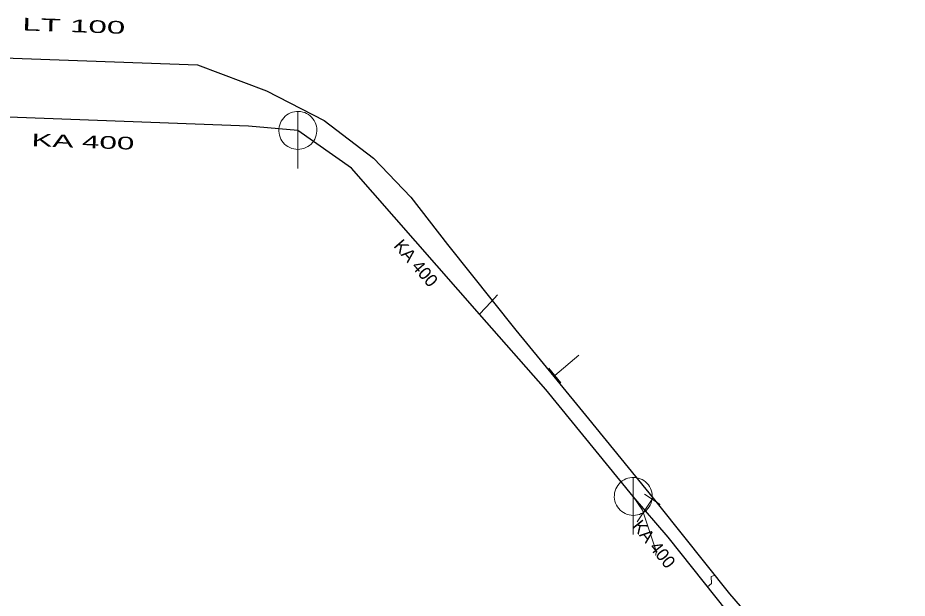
# Model space of a CAD drawing. Extents: x -688432 to -687974, y -973332 to -972704.
# Drawn here: x -688097.06 to -688050.24, y -972954.25 to -972923.69 of the extents above; entities that cross this region are included whole.
import ezdxf
from ezdxf.enums import TextEntityAlignment as Align

# ---------------------------------------------------------------- set-up
doc = ezdxf.new("R2010")
doc.units = 0
doc.header["$LTSCALE"] = 0.27
for name, color, linetype, lineweight in [('1', 7, 'Continuous', 25), ('11', 7, 'Continuous', 13), ('13', 7, 'Continuous', 13), ('14', 7, 'Continuous', 25), ('17', 7, 'Continuous', 25), ('22', 7, 'Continuous', 13), ('34', 7, 'Continuous', 13)]:
    doc.layers.add(name, color=color, linetype=linetype, lineweight=lineweight)

msp = doc.modelspace()

# ---------------------------------------------------------------- linework, layer by layer
at = {"layer": '11'}
for points in [[(-688071.809, -972938.28), (-688072.149, -972938.64), (-688072.75, -972939.3)], [(-688063.48, -972952), (-688063.449, -972951.77), (-688064.17, -972949.609), (-688064.66, -972948.89)], [(-688060.41, -972953.05), (-688060.559, -972953.1), (-688060.539, -972953.48), (-688060.75, -972953.649)]]:
    msp.add_lwpolyline(points, dxfattribs=at)
at = {"layer": '13'}
for p, q in [((-688068.793, -972942.522), (-688067.52, -972941.449)), ((-688063.661, -972949.042), (-688064.449, -972950.219))]:
    msp.add_line(p, q, dxfattribs=at)
at = {"layer": '14', "lineweight": 13}
for p, q in [((-688068.85, -972942.57), (-688068.793, -972942.522)), ((-688063.62, -972948.98), (-688063.661, -972949.042))]:
    msp.add_line(p, q, dxfattribs=at)
at = {"layer": '14'}
for points in [[(-688082.32, -972929.62), (-688084.92, -972929.39), (-688102.239, -972928.739)], [(-688064.66, -972948.89), (-688069.27, -972943.26), (-688072.75, -972939.3), (-688079.5, -972931.6), (-688082.32, -972929.62)], [(-688056.879, -972958.18), (-688059.07, -972955.76), (-688062.829, -972951.039), (-688064.66, -972948.89)]]:
    msp.add_lwpolyline(points, dxfattribs=at)
at = {"layer": '17'}
msp.add_lwpolyline([(-688142.539, -972926.989), (-688136.969, -972927.03), (-688124.52, -972926.469), (-688116.5, -972926.3), (-688115.02, -972926.289), (-688112.359, -972926.21), (-688100.73, -972925.699), (-688087.609, -972926.17), (-688083.969, -972927.539), (-688080.94, -972929.1), (-688078.329, -972931.09), (-688076.37, -972933.14), (-688074.449, -972935.62), (-688070.85, -972940.129), (-688068.85, -972942.57), (-688067.02, -972944.8), (-688063.62, -972948.98), (-688063.329, -972949.34), (-688059.6, -972954.02), (-688058.039, -972955.829), (-688055.76, -972958.48), (-688051.969, -972962.76), (-688050.239, -972964.93)], dxfattribs=at)
at = {"layer": '22'}
for p, q in [((-688082.32, -972931.62), (-688082.319, -972928.62)), ((-688064.66, -972950.89), (-688064.659, -972947.89))]:
    msp.add_line(p, q, dxfattribs=at)
for points in [[(-688081.32, -972929.62), (-688081.325, -972929.511), (-688081.343, -972929.403), (-688081.373, -972929.297), (-688081.413, -972929.196), (-688081.465, -972929.099), (-688081.527, -972929.009), (-688081.599, -972928.926), (-688081.679, -972928.852), (-688081.767, -972928.786), (-688081.861, -972928.731), (-688081.961, -972928.686), (-688082.066, -972928.653), (-688082.173, -972928.631), (-688082.282, -972928.621), (-688082.392, -972928.623), (-688082.5, -972928.637), (-688082.607, -972928.662), (-688082.71, -972928.699), (-688082.808, -972928.748), (-688082.9, -972928.806), (-688082.986, -972928.875), (-688083.063, -972928.952), (-688083.132, -972929.038), (-688083.191, -972929.13), (-688083.239, -972929.228), (-688083.276, -972929.331), (-688083.302, -972929.438), (-688083.316, -972929.546), (-688083.319, -972929.656), (-688083.309, -972929.765), (-688083.288, -972929.872), (-688083.254, -972929.976), (-688083.21, -972930.076), (-688083.155, -972930.171), (-688083.089, -972930.259), (-688083.015, -972930.339), (-688082.932, -972930.411), (-688082.842, -972930.473), (-688082.746, -972930.525), (-688082.644, -972930.566), (-688082.539, -972930.596), (-688082.431, -972930.614), (-688082.321, -972930.62), (-688082.212, -972930.614), (-688082.104, -972930.596), (-688081.999, -972930.567), (-688081.897, -972930.526), (-688081.8, -972930.474), (-688081.71, -972930.412), (-688081.627, -972930.341), (-688081.552, -972930.261), (-688081.487, -972930.173), (-688081.431, -972930.079), (-688081.387, -972929.979), (-688081.353, -972929.875), (-688081.331, -972929.767), (-688081.321, -972929.658)], [(-688063.66, -972948.89), (-688063.665, -972948.781), (-688063.683, -972948.673), (-688063.713, -972948.567), (-688063.753, -972948.466), (-688063.805, -972948.369), (-688063.867, -972948.279), (-688063.939, -972948.196), (-688064.019, -972948.122), (-688064.107, -972948.056), (-688064.201, -972948.001), (-688064.301, -972947.956), (-688064.406, -972947.923), (-688064.513, -972947.901), (-688064.622, -972947.891), (-688064.732, -972947.893), (-688064.84, -972947.907), (-688064.947, -972947.932), (-688065.05, -972947.969), (-688065.148, -972948.018), (-688065.24, -972948.076), (-688065.326, -972948.145), (-688065.403, -972948.222), (-688065.472, -972948.308), (-688065.531, -972948.4), (-688065.579, -972948.498), (-688065.616, -972948.601), (-688065.642, -972948.708), (-688065.656, -972948.816), (-688065.659, -972948.926), (-688065.649, -972949.035), (-688065.628, -972949.142), (-688065.594, -972949.246), (-688065.55, -972949.346), (-688065.495, -972949.441), (-688065.429, -972949.529), (-688065.355, -972949.609), (-688065.272, -972949.681), (-688065.182, -972949.743), (-688065.086, -972949.795), (-688064.984, -972949.836), (-688064.879, -972949.866), (-688064.771, -972949.884), (-688064.661, -972949.89), (-688064.552, -972949.884), (-688064.444, -972949.866), (-688064.339, -972949.837), (-688064.237, -972949.796), (-688064.14, -972949.744), (-688064.05, -972949.682), (-688063.967, -972949.611), (-688063.892, -972949.531), (-688063.827, -972949.443), (-688063.771, -972949.349), (-688063.727, -972949.249), (-688063.693, -972949.145), (-688063.671, -972949.037), (-688063.661, -972948.928)]]:
    msp.add_lwpolyline(points, close=True, dxfattribs=at)
at = {"layer": '34'}
for p, q in [((-688069.115, -972942.139), (-688068.471, -972942.904)), ((-688063.245, -972949.319), (-688064.076, -972948.763))]:
    msp.add_line(p, q, dxfattribs=at)

# ---------------------------------------------------------------- texts
at = {"layer": '1'}
for s, width, p in [('LT 100', 1.95, (-688094.1256, -972924.4473)), ('LT 100', 1.95, (-688094.1256, -972924.4473)), ('LT 100', 1.95, (-688094.1256, -972924.4473)), ('LT 100', 1.95, (-688094.1256, -972924.4473)), ('LT 100', 1.95, (-688094.1256, -972924.4473)), ('KA 400', 1.85, (-688093.6446, -972930.5413)), ('KA 400', 1.85, (-688093.6446, -972930.5413)), ('KA 400', 1.85, (-688093.6446, -972930.5413)), ('KA 400', 1.85, (-688093.6446, -972930.5413)), ('KA 400', 1.85, (-688093.6446, -972930.5413))]:
    msp.add_text(s, height=0.6667, rotation=358, dxfattribs=dict(at, width=width)).set_placement(p, align=Align.CENTER)
for rotation, p in [(311, (-688076.3515, -972936.8239)), (311, (-688076.3515, -972936.8239)), (311, (-688076.3515, -972936.8239)), (311, (-688076.3515, -972936.8239)), (311, (-688076.3515, -972936.8239)), (309, (-688063.8257, -972951.6058)), (309, (-688063.8257, -972951.6058)), (309, (-688063.8257, -972951.6058)), (309, (-688063.8257, -972951.6058)), (309, (-688063.8257, -972951.6058))]:
    msp.add_text('KA 400', height=0.6667, rotation=rotation, dxfattribs=at).set_placement(p, align=Align.CENTER)

doc.saveas('drawing.dxf')
